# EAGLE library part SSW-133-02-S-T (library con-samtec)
THROUGH-HOLE .025" SQ POST SOCKET Source: Samtec SSW.pdf
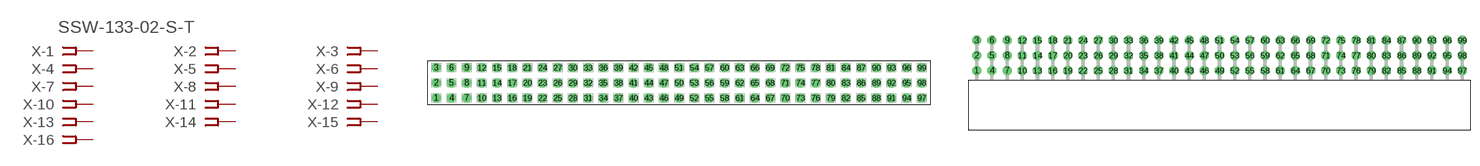
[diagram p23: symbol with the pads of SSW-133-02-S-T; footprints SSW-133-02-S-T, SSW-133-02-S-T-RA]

Designator prefix X; gates -1=FPINV -2=FPIN -3=FPIN -4=FPIN -5=FPIN -6=FPIN -7=FPIN -8=FPIN -9=FPIN -10=FPIN -11=FPIN -12=FPIN -13=FPIN -14=FPIN -15=FPIN -16=FPIN -17=FPIN -18=FPIN -19=FPIN -20=FPIN -21=FPIN -22=FPIN -23=FPIN -24=FPIN -25=FPIN -26=FPIN -27=FPIN -28=FPIN -29=FPIN -30=FPIN -31=FPIN -32=FPIN -33=FPIN -34=FPIN -35=FPIN -36=FPIN -37=FPIN -38=FPIN -39=FPIN -40=FPIN -41=FPIN -42=FPIN -43=FPIN -44=FPIN -45=FPIN -46=FPIN -47=FPIN -48=FPIN -49=FPIN -50=FPIN -51=FPIN -52=FPIN -53=FPIN -54=FPIN -55=FPIN -56=FPIN -57=FPIN -58=FPIN -59=FPIN -60=FPIN -61=FPIN -62=FPIN -63=FPIN -64=FPIN -65=FPIN -66=FPIN -67=FPIN -68=FPIN -69=FPIN -70=FPIN -71=FPIN -72=FPIN -73=FPIN -74=FPIN -75=FPIN -76=FPIN -77=FPIN -78=FPIN -79=FPIN -80=FPIN -81=FPIN -82=FPIN -83=FPIN -84=FPIN -85=FPIN -86=FPIN -87=FPIN -88=FPIN -89=FPIN -90=FPIN -91=FPIN -92=FPIN -93=FPIN -94=FPIN -95=FPIN -96=FPIN -97=FPIN -98=FPIN -99=FPIN

## SSW-133-02-S-T (OC_FARNELL: unknown; OC_NEWARK: unknown)  [SSW-133-02-S-T]
1  -1:1  pas
2  -2:1  pas
3  -3:1  pas
4  -4:1  pas
5  -5:1  pas
6  -6:1  pas
7  -7:1  pas
8  -8:1  pas
9  -9:1  pas
10  -10:1  pas
11  -11:1  pas
12  -12:1  pas
13  -13:1  pas
14  -14:1  pas
15  -15:1  pas
16  -16:1  pas
17  -17:1  pas
18  -18:1  pas
19  -19:1  pas
20  -20:1  pas
21  -21:1  pas
22  -22:1  pas
23  -23:1  pas
24  -24:1  pas
25  -25:1  pas
26  -26:1  pas
27  -27:1  pas
28  -28:1  pas
29  -29:1  pas
30  -30:1  pas
31  -31:1  pas
32  -32:1  pas
33  -33:1  pas
34  -34:1  pas
35  -35:1  pas
36  -36:1  pas
37  -37:1  pas
38  -38:1  pas
39  -39:1  pas
40  -40:1  pas
41  -41:1  pas
42  -42:1  pas
43  -43:1  pas
44  -44:1  pas
45  -45:1  pas
46  -46:1  pas
47  -47:1  pas
48  -48:1  pas
49  -49:1  pas
50  -50:1  pas
51  -51:1  pas
52  -52:1  pas
53  -53:1  pas
54  -54:1  pas
55  -55:1  pas
56  -56:1  pas
57  -57:1  pas
58  -58:1  pas
59  -59:1  pas
60  -60:1  pas
61  -61:1  pas
62  -62:1  pas
63  -63:1  pas
64  -64:1  pas
65  -65:1  pas
66  -66:1  pas
67  -67:1  pas
68  -68:1  pas
69  -69:1  pas
70  -70:1  pas
71  -71:1  pas
72  -72:1  pas
73  -73:1  pas
74  -74:1  pas
75  -75:1  pas
76  -76:1  pas
77  -77:1  pas
78  -78:1  pas
79  -79:1  pas
80  -80:1  pas
81  -81:1  pas
82  -82:1  pas
83  -83:1  pas
84  -84:1  pas
85  -85:1  pas
86  -86:1  pas
87  -87:1  pas
88  -88:1  pas
89  -89:1  pas
90  -90:1  pas
91  -91:1  pas
92  -92:1  pas
93  -93:1  pas
94  -94:1  pas
95  -95:1  pas
96  -96:1  pas
97  -97:1  pas
98  -98:1  pas
99  -99:1  pas

## SSW-133-02-S-TRA (MPN: SSW-133-02-S-T-RA; OC_FARNELL: unknown; OC_NEWARK: 83P0555)  [SSW-133-02-S-T-RA]
Pads as for SSW-133-02-S-T

## Footprint SSW-133-02-S-T (pad centres in mm)
THROUGH-HOLE .025" SQ POST SOCKET Source: Samtec SSW.pdf
drill 1 pad 1.5 octagon: 1 -40.64,-2.54; 2 -40.64,0; 3 -40.64,2.54; 4 -38.1,-2.54; 5 -38.1,0; 6 -38.1,2.54; 7 -35.56,-2.54; 8 -35.56,0; 9 -35.56,2.54; 10 -33.02,-2.54; 11 -33.02,0; 12 -33.02,2.54; 13 -30.48,-2.54; 14 -30.48,0; 15 -30.48,2.54; 16 -27.94,-2.54; 17 -27.94,0; 18 -27.94,2.54; 19 -25.4,-2.54; 20 -25.4,0; 21 -25.4,2.54; 22 -22.86,-2.54; 23 -22.86,0; 24 -22.86,2.54; 25 -20.32,-2.54; 26 -20.32,0; 27 -20.32,2.54; 28 -17.78,-2.54; 29 -17.78,0; 30 -17.78,2.54; 31 -15.24,-2.54; 32 -15.24,0; 33 -15.24,2.54; 34 -12.7,-2.54; 35 -12.7,0; 36 -12.7,2.54; 37 -10.16,-2.54; 38 -10.16,0; 39 -10.16,2.54; 40 -7.62,-2.54; 41 -7.62,0; 42 -7.62,2.54; 43 -5.08,-2.54; 44 -5.08,0; 45 -5.08,2.54; 46 -2.54,-2.54; 47 -2.54,0; 48 -2.54,2.54; 49 0,-2.54; 50 0,0; 51 0,2.54; 52 2.54,-2.54; 53 2.54,0; 54 2.54,2.54; 55 5.08,-2.54; 56 5.08,0; 57 5.08,2.54; 58 7.62,-2.54; 59 7.62,0; 60 7.62,2.54; 61 10.16,-2.54; 62 10.16,0; 63 10.16,2.54; 64 12.7,-2.54; 65 12.7,0; 66 12.7,2.54; 67 15.24,-2.54; 68 15.24,0; 69 15.24,2.54; 70 17.78,-2.54; 71 17.78,0; 72 17.78,2.54; 73 20.32,-2.54; 74 20.32,0; 75 20.32,2.54; 76 22.86,-2.54; 77 22.86,0; 78 22.86,2.54; 79 25.4,-2.54; 80 25.4,0; 81 25.4,2.54; 82 27.94,-2.54; 83 27.94,0; 84 27.94,2.54; 85 30.48,-2.54; 86 30.48,0; 87 30.48,2.54; 88 33.02,-2.54; 89 33.02,0; 90 33.02,2.54; 91 35.56,-2.54; 92 35.56,0; 93 35.56,2.54; 94 38.1,-2.54; 95 38.1,0; 96 38.1,2.54; 97 40.64,-2.54; 98 40.64,0; 99 40.64,2.54

## Footprint SSW-133-02-S-T-RA (pad centres in mm)
THROUGH-HOLE .025" SQ POST SOCKET Source: Samtec SSW.pdf
drill 1 pad 1.5 octagon: 1 -40.64,1.524; 2 -40.64,4.064; 3 -40.64,6.604; 4 -38.1,1.524; 5 -38.1,4.064; 6 -38.1,6.604; 7 -35.56,1.524; 8 -35.56,4.064; 9 -35.56,6.604; 10 -33.02,1.524; 11 -33.02,4.064; 12 -33.02,6.604; 13 -30.48,1.524; 14 -30.48,4.064; 15 -30.48,6.604; 16 -27.94,1.524; 17 -27.94,4.064; 18 -27.94,6.604; 19 -25.4,1.524; 20 -25.4,4.064; 21 -25.4,6.604; 22 -22.86,1.524; 23 -22.86,4.064; 24 -22.86,6.604; 25 -20.32,1.524; 26 -20.32,4.064; 27 -20.32,6.604; 28 -17.78,1.524; 29 -17.78,4.064; 30 -17.78,6.604; 31 -15.24,1.524; 32 -15.24,4.064; 33 -15.24,6.604; 34 -12.7,1.524; 35 -12.7,4.064; 36 -12.7,6.604; 37 -10.16,1.524; 38 -10.16,4.064; 39 -10.16,6.604; 40 -7.62,1.524; 41 -7.62,4.064; 42 -7.62,6.604; 43 -5.08,1.524; 44 -5.08,4.064; 45 -5.08,6.604; 46 -2.54,1.524; 47 -2.54,4.064; 48 -2.54,6.604; 49 0,1.524; 50 0,4.064; 51 0,6.604; 52 2.54,1.524; 53 2.54,4.064; 54 2.54,6.604; 55 5.08,1.524; 56 5.08,4.064; 57 5.08,6.604; 58 7.62,1.524; 59 7.62,4.064; 60 7.62,6.604; 61 10.16,1.524; 62 10.16,4.064; 63 10.16,6.604; 64 12.7,1.524; 65 12.7,4.064; 66 12.7,6.604; 67 15.24,1.524; 68 15.24,4.064; 69 15.24,6.604; 70 17.78,1.524; 71 17.78,4.064; 72 17.78,6.604; 73 20.32,1.524; 74 20.32,4.064; 75 20.32,6.604; 76 22.86,1.524; 77 22.86,4.064; 78 22.86,6.604; 79 25.4,1.524; 80 25.4,4.064; 81 25.4,6.604; 82 27.94,1.524; 83 27.94,4.064; 84 27.94,6.604; 85 30.48,1.524; 86 30.48,4.064; 87 30.48,6.604; 88 33.02,1.524; 89 33.02,4.064; 90 33.02,6.604; 91 35.56,1.524; 92 35.56,4.064; 93 35.56,6.604; 94 38.1,1.524; 95 38.1,4.064; 96 38.1,6.604; 97 40.64,1.524; 98 40.64,4.064; 99 40.64,6.604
